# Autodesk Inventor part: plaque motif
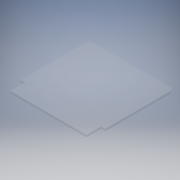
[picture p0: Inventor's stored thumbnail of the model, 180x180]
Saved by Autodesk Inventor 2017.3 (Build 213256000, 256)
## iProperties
Part Number: plaque motif
Material: Plastique PMMA
Document SubType Name: Modeling
Designer: ficho
Density: 1.188 g/cm^3
Appearance: Transparent - Clair
Author: ficho
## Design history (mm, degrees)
sketch "Esquisse1"
  geometry: L1 (0, 0)-(123, 0) reference; L2 (0, 0)-(0, -3) reference; L3 (0, -3)-(6, -3) reference; L4 (6, -3)-(6, -4.5) reference; L5 (6, -4.5)-(6, -24.5) reference; L6 (6, -24.5)-(117, -24.5) reference; L7 (117, -24.5)-(117, -4.5) reference; L8 (117, -3)-(117, -4.5) reference; L9 (117, -3)-(123, -3) reference; L10 (123, 0)-(123, -3) reference; L11 (123, -3)-(123, 92); L12 (118, 97)-(5, 97); L13 (0, 92)-(0, -3); L14 (8, -24.5)-(115, -24.5); L15 (117, -22.5)-(117, -3); L16 (6, -3)-(6, -22.5); L17 (6, -22.5)-(8, -24.5); L18 (117, -22.5)-(115, -24.5); L19 (0, -3)-(6, -3); L20 (117, -3)-(123, -3); C1 r 1.5 at (11, -17); C2 r 1.5 at (11, -17); C3 r 1.5 at (112, -17); A1 r 5 centre (5, 92) between (5, 97) and (0, 92); A2 r 5 centre (118, 92) between (123, 92) and (118, 97); 1 further point
  constraints: 20 end point, 5 centre point, 4 parallel, 4 point on circle, 4 point on line, 4 tangent, 3 horizontal, 3 perpendicular, 2 equal radius, 1 coincident
  dimensions: "d0" = 2 distance of L16.end L5.end; "d1" = 2 distance of L14.start L5.end (= d0); "d2" = 2 distance of L15.start point (117, -24.5) (= d0); "d3" = 2 distance of L14.end point (117, -24.5) (= d2); "d5" = 5 radius of A1; "d8" = 3 diameter of C3; "d9" = 3 diameter of C1
extrude "Extrusion1" new body sketch "Esquisse1" distance "d6" = 3; taper "d7" = 0 deg
node "Solide1"
